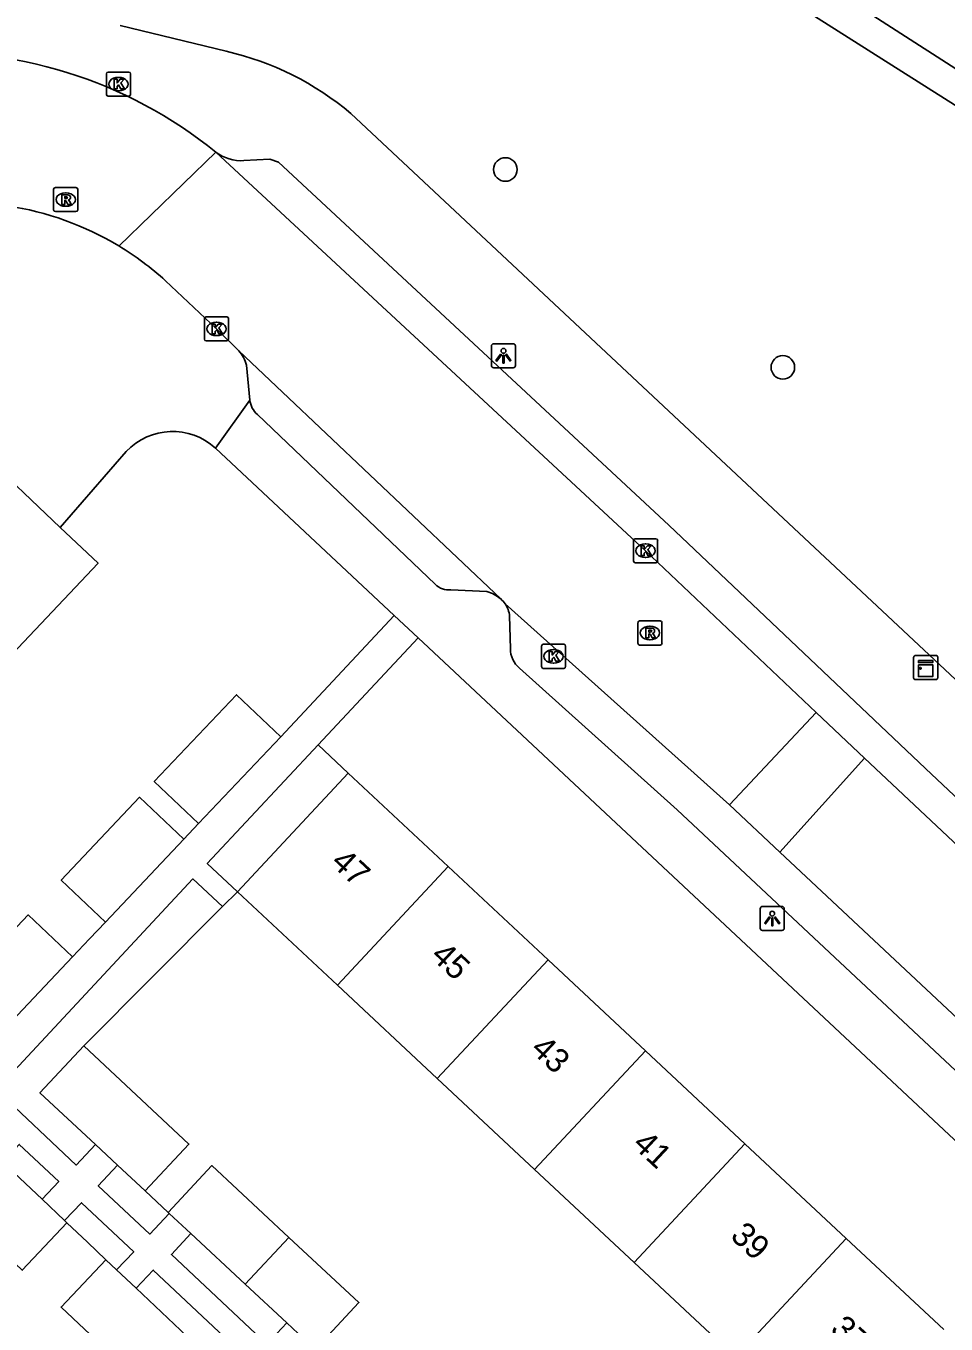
# Model space of a CAD drawing. Extents: x 159040 to 160094, y 381214 to 382518.
# Drawn here: x 159293.6 to 159331.8, y 381642.3 to 381696.1 of the extents above; entities that cross this region are included whole.
import ezdxf

# ---------------------------------------------------------------- set-up
doc = ezdxf.new("R2010")
doc.units = 0
for name, color, linetype in [('IMGEO_Boom', 7, 'Continuous'), ('IMGEO_Groenvoorziening', 7, 'Continuous'), ('IMGEO_Kast', 7, 'Continuous'), ('IMGEO_Kolk', 7, 'Continuous'), ('IMGEO_Lichtpunt', 7, 'Continuous'), ('IMGEO_Pand', 7, 'Continuous'), ('IMGEO_Pand_nummerreeks', 7, 'Continuous'), ('IMGEO_Pand_vergunning_verleend', 7, 'Continuous'), ('IMGEO_Rijbaan_lokaal_open', 7, 'Continuous'), ('IMGEO_Rioolput', 7, 'Continuous'), ('IMGEO_Voetpad_open', 7, 'Continuous')]:
    doc.layers.add(name, color=color, linetype=linetype)

msp = doc.modelspace()

# ---------------------------------------------------------------- linework, layer by layer
at = {"layer": 'IMGEO_Boom'}
for centre in [(159313.485, 381690.153), (159324.991, 381681.949)]:
    msp.add_circle(centre, 0.489, dxfattribs=at)
at = {"layer": 'IMGEO_Groenvoorziening'}
for points in [[(159254.046, 381759.615), (159260.693, 381743.327), (159266.405, 381734.562), (159282.762, 381724.205), (159299.545, 381713.576), (159301.255, 381712.388), (159329.506, 381694.484), (159334.296, 381691.448), (159363.507, 381691.862)], [(159305.726, 381666.298), (159306.973, 381665.131)], [(159301.759, 381659.594), (159296, 381653.818)], [(159298.548, 381647.807), (159299.504, 381646.915)], [(159295.298, 381646.49), (159296.153, 381645.681), (159296.923, 381644.952)]]:
    msp.add_lwpolyline(points, dxfattribs=at)
at = {"layer": 'IMGEO_Kast'}
for p, q in [((159330.489, 381670.007), (159331.33, 381670.007)), ((159331.33, 381670.007), (159330.489, 381670.007)), ((159331.414, 381669.932), (159331.414, 381669.091)), ((159331.414, 381669.091), (159331.414, 381669.932)), ((159330.414, 381669.082), (159330.414, 381669.923)), ((159330.414, 381669.923), (159330.414, 381669.082)), ((159331.339, 381669.007), (159330.498, 381669.007)), ((159330.498, 381669.007), (159331.339, 381669.007))]:
    msp.add_line(p, q, dxfattribs=at)
for points in [[(159330.609, 381669.797), (159331.209, 381669.797), (159331.209, 381669.712), (159330.609, 381669.712), (159330.609, 381669.797)], [(159330.609, 381669.622), (159331.209, 381669.622), (159331.209, 381669.133), (159330.609, 381669.133), (159330.609, 381669.622)]]:
    msp.add_lwpolyline(points, dxfattribs=at)
msp.add_circle((159330.693, 381669.471), 0.0377, dxfattribs=at)
for centre, start, end in [((159330.492, 381669.929), 92.4484, 184.2845), ((159330.492, 381669.929), 92.4484, 184.2845), ((159331.336, 381669.929), 2.4484, 94.2845), ((159331.336, 381669.929), 2.4484, 94.2845), ((159330.492, 381669.085), 182.4484, 274.2845), ((159330.492, 381669.085), 182.4484, 274.2845), ((159331.336, 381669.085), 272.4484, 4.2845), ((159331.336, 381669.085), 272.4484, 4.2845)]:
    msp.add_arc(centre, 0.0779, start, end, dxfattribs=at)
at = {"layer": 'IMGEO_Kolk'}
for p, q in [((159297.017, 381694.192), (159297.869, 381694.192)), ((159296.942, 381693.266), (159296.942, 381694.118)), ((159297.43, 381693.972), (159297.455, 381693.972)), ((159297.943, 381694.118), (159297.943, 381693.266)), ((159297.869, 381693.192), (159297.017, 381693.192)), ((159297.453, 381693.412), (159297.428, 381693.412)), ((159301.006, 381683.118), (159301.006, 381683.97)), ((159301.081, 381684.044), (159301.933, 381684.044)), ((159302.007, 381683.97), (159302.007, 381683.118)), ((159301.494, 381683.824), (159301.519, 381683.824)), ((159301.933, 381683.044), (159301.081, 381683.044)), ((159301.517, 381683.264), (159301.492, 381683.264)), ((159318.798, 381673.921), (159318.798, 381674.773)), ((159318.873, 381674.847), (159319.725, 381674.847)), ((159319.799, 381674.773), (159319.799, 381673.921)), ((159319.286, 381674.627), (159319.311, 381674.627)), ((159319.725, 381673.847), (159318.873, 381673.847)), ((159319.309, 381674.067), (159319.284, 381674.067)), ((159315.057, 381670.469), (159315.909, 381670.469)), ((159314.982, 381669.543), (159314.982, 381670.395)), ((159315.47, 381670.249), (159315.495, 381670.249)), ((159315.983, 381670.395), (159315.983, 381669.543)), ((159315.909, 381669.469), (159315.057, 381669.469)), ((159315.493, 381669.689), (159315.468, 381669.689))]:
    msp.add_line(p, q, dxfattribs=at)
for points in [[(159297.017, 381694.192), (159297.869, 381694.192)], [(159296.942, 381693.266), (159296.942, 381694.118)], [(159297.263, 381693.892), (159297.386, 381693.892), (159297.386, 381693.741), (159297.516, 381693.892), (159297.68, 381693.892), (159297.534, 381693.741), (159297.687, 381693.492), (159297.535, 381693.492), (159297.45, 381693.656), (159297.386, 381693.589), (159297.386, 381693.492), (159297.263, 381693.492), (159297.263, 381693.892)], [(159297.943, 381694.118), (159297.943, 381693.266)], [(159297.869, 381693.192), (159297.017, 381693.192)], [(159301.006, 381683.118), (159301.006, 381683.97)], [(159301.081, 381684.044), (159301.933, 381684.044)], [(159302.007, 381683.97), (159302.007, 381683.118)], [(159301.327, 381683.744), (159301.45, 381683.744), (159301.45, 381683.593), (159301.58, 381683.744), (159301.744, 381683.744), (159301.598, 381683.593), (159301.751, 381683.344), (159301.599, 381683.344), (159301.514, 381683.508), (159301.45, 381683.441), (159301.45, 381683.344), (159301.327, 381683.344), (159301.327, 381683.744)], [(159301.933, 381683.044), (159301.081, 381683.044)], [(159318.798, 381673.921), (159318.798, 381674.773)], [(159318.873, 381674.847), (159319.725, 381674.847)], [(159319.799, 381674.773), (159319.799, 381673.921)], [(159319.119, 381674.547), (159319.242, 381674.547), (159319.242, 381674.396), (159319.372, 381674.547), (159319.536, 381674.547), (159319.39, 381674.396), (159319.543, 381674.147), (159319.391, 381674.147), (159319.306, 381674.311), (159319.242, 381674.244), (159319.242, 381674.147), (159319.119, 381674.147), (159319.119, 381674.547)], [(159319.725, 381673.847), (159318.873, 381673.847)], [(159315.057, 381670.469), (159315.909, 381670.469)], [(159314.982, 381669.543), (159314.982, 381670.395)], [(159315.303, 381670.169), (159315.426, 381670.169), (159315.426, 381670.018), (159315.556, 381670.169), (159315.72, 381670.169), (159315.574, 381670.018), (159315.727, 381669.769), (159315.575, 381669.769), (159315.49, 381669.933), (159315.426, 381669.866), (159315.426, 381669.769), (159315.303, 381669.769), (159315.303, 381670.169)], [(159315.983, 381670.395), (159315.983, 381669.543)], [(159315.909, 381669.469), (159315.057, 381669.469)]]:
    msp.add_lwpolyline(points, dxfattribs=at)
for centre, start, end in [((159297.019, 381694.116), 91.552, 178.448), ((159297.019, 381694.116), 91.552, 178.448), ((159297.867, 381694.116), 1.552, 88.448), ((159297.867, 381694.116), 1.552, 88.448), ((159297.019, 381693.268), 181.552, 268.448), ((159297.019, 381693.268), 181.552, 268.448), ((159297.867, 381693.268), 271.552, 358.448), ((159297.867, 381693.268), 271.552, 358.448), ((159301.083, 381683.968), 91.552, 178.448), ((159301.083, 381683.968), 91.552, 178.448), ((159301.931, 381683.968), 1.552, 88.448), ((159301.931, 381683.968), 1.552, 88.448), ((159301.083, 381683.12), 181.552, 268.448), ((159301.083, 381683.12), 181.552, 268.448), ((159301.931, 381683.12), 271.552, 358.448), ((159301.931, 381683.12), 271.552, 358.448), ((159318.875, 381674.771), 91.552, 178.448), ((159318.875, 381674.771), 91.552, 178.448), ((159319.723, 381674.771), 1.552, 88.448), ((159319.723, 381674.771), 1.552, 88.448), ((159318.875, 381673.923), 181.552, 268.448), ((159318.875, 381673.923), 181.552, 268.448), ((159319.723, 381673.923), 271.552, 358.448), ((159319.723, 381673.923), 271.552, 358.448), ((159315.059, 381670.393), 91.552, 178.448), ((159315.059, 381670.393), 91.552, 178.448), ((159315.907, 381670.393), 1.552, 88.448), ((159315.907, 381670.393), 1.552, 88.448), ((159315.059, 381669.545), 181.552, 268.448), ((159315.059, 381669.545), 181.552, 268.448), ((159315.907, 381669.545), 271.552, 358.448), ((159315.907, 381669.545), 271.552, 358.448)]:
    msp.add_arc(centre, 0.0765, start, end, dxfattribs=at)
for centre, major_axis, ratio, start_param, end_param in [((159297.429, 381693.692), (-0.387, 0.002), 0.722429, 4.712389, 7.853982), ((159297.454, 381693.692), (-0.39, 0.002), 0.717154, 1.570796, 4.712389), ((159301.493, 381683.544), (-0.387, 0.002), 0.722429, 4.712389, 7.853982), ((159301.518, 381683.544), (-0.39, 0.002), 0.717154, 1.570796, 4.712389), ((159319.285, 381674.347), (-0.387, 0.002), 0.722429, 4.712389, 7.853982), ((159319.31, 381674.347), (-0.39, 0.002), 0.717154, 1.570796, 4.712389), ((159315.469, 381669.969), (-0.387, 0.002), 0.722429, 4.712389, 7.853982), ((159315.494, 381669.969), (-0.39, 0.002), 0.717154, 1.570796, 4.712389)]:
    msp.add_ellipse(centre, major_axis=major_axis, ratio=ratio, start_param=start_param, end_param=end_param, dxfattribs=at)
at = {"layer": 'IMGEO_Lichtpunt'}
for p, q in [((159313.809, 381682.931), (159313.001, 381682.931)), ((159313.809, 381682.931), (159313.001, 381682.931)), ((159312.907, 381682.836), (159312.907, 381682.029)), ((159312.907, 381682.836), (159312.907, 381682.029)), ((159313.903, 381682.029), (159313.903, 381682.836)), ((159313.903, 381682.029), (159313.903, 381682.836)), ((159313.001, 381681.935), (159313.809, 381681.935)), ((159313.001, 381681.935), (159313.809, 381681.935)), ((159324.052, 381659.505), (159324.052, 381658.698)), ((159324.052, 381659.505), (159324.052, 381658.698)), ((159324.954, 381659.6), (159324.146, 381659.6)), ((159324.954, 381659.6), (159324.146, 381659.6)), ((159325.048, 381658.698), (159325.048, 381659.505)), ((159325.048, 381658.698), (159325.048, 381659.505)), ((159324.146, 381658.604), (159324.954, 381658.604)), ((159324.146, 381658.604), (159324.954, 381658.604))]:
    msp.add_line(p, q, dxfattribs=at)
for points in [[(159313.281, 381682.5), (159313.32, 381682.472), (159313.132, 381682.21), (159313.094, 381682.237), (159313.281, 381682.5)], [(159313.383, 381682.452), (159313.43, 381682.452), (159313.43, 381682.13), (159313.383, 381682.13), (159313.383, 381682.452)], [(159313.493, 381682.472), (159313.531, 381682.499), (159313.718, 381682.237), (159313.679, 381682.209), (159313.493, 381682.472)], [(159324.426, 381659.169), (159324.465, 381659.141), (159324.277, 381658.879), (159324.239, 381658.906), (159324.426, 381659.169)], [(159324.638, 381659.141), (159324.676, 381659.168), (159324.863, 381658.906), (159324.824, 381658.878), (159324.638, 381659.141)], [(159324.528, 381659.121), (159324.575, 381659.121), (159324.575, 381658.799), (159324.528, 381658.799), (159324.528, 381659.121)]]:
    msp.add_lwpolyline(points, dxfattribs=at)
for centre in [(159313.406, 381682.634), (159324.551, 381659.303)]:
    msp.add_circle(centre, 0.0994, dxfattribs=at)
for centre, start, end in [((159313.001, 381682.836), 90, 180), ((159313.001, 381682.836), 90, 180), ((159313.809, 381682.836), 0, 90), ((159313.809, 381682.836), 0, 90), ((159313.001, 381682.029), 180, 270), ((159313.001, 381682.029), 180, 270), ((159313.809, 381682.029), 270, 0), ((159313.809, 381682.029), 270, 360), ((159324.146, 381659.505), 90, 180), ((159324.146, 381659.505), 90, 180), ((159324.954, 381659.505), 0, 90), ((159324.954, 381659.505), 0, 90), ((159324.146, 381658.698), 180, 270), ((159324.146, 381658.698), 180, 270), ((159324.954, 381658.698), 270, 0), ((159324.954, 381658.698), 270, 360)]:
    msp.add_arc(centre, 0.0946, start, end, dxfattribs=at)
at = {"layer": 'IMGEO_Pand'}
for points in [[(159291.702, 381678.458), (159295.025, 381675.313)], [(159295.025, 381675.313), (159296.595, 381673.828), (159292.562, 381669.565)], [(159304.176, 381666.638), (159302.337, 381668.378), (159298.927, 381664.774), (159300.766, 381663.034)], [(159300.766, 381663.034), (159304.176, 381666.638)], [(159302.373, 381660.209), (159306.973, 381665.131)], [(159306.973, 381665.131), (159311.117, 381661.258)], [(159300.152, 381662.385), (159298.313, 381664.125), (159295.068, 381660.695), (159296.907, 381658.955)], [(159296.907, 381658.955), (159300.152, 381662.385)], [(159306.518, 381656.336), (159311.117, 381661.258)], [(159311.117, 381661.258), (159315.262, 381657.384)], [(159306.518, 381656.336), (159302.373, 381660.209)], [(159295.537, 381657.507), (159293.698, 381659.247), (159290.481, 381655.846)], [(159292.32, 381654.107), (159295.537, 381657.507)], [(159310.663, 381652.462), (159315.262, 381657.384)], [(159315.262, 381657.384), (159319.291, 381653.619)], [(159310.663, 381652.462), (159306.518, 381656.336)], [(159296.49, 381649.727), (159294.187, 381651.875), (159296, 381653.818)], [(159296, 381653.818), (159300.363, 381649.749), (159298.548, 381647.807)], [(159319.291, 381653.619), (159314.692, 381648.697)], [(159319.291, 381653.619), (159323.418, 381649.763)], [(159314.692, 381648.697), (159310.663, 381652.462)], [(159296.49, 381649.727), (159297.408, 381648.87)], [(159318.819, 381644.84), (159323.418, 381649.763)], [(159323.418, 381649.763), (159327.622, 381645.834)], [(159294.273, 381647.46), (159292.641, 381649.003)], [(159298.548, 381647.807), (159297.408, 381648.87)], [(159299.504, 381646.915), (159301.319, 381648.857), (159304.512, 381645.879)], [(159318.819, 381644.84), (159314.692, 381648.697)], [(159295.298, 381646.49), (159293.452, 381644.514), (159290.242, 381647.551)], [(159295.205, 381646.578), (159294.273, 381647.46)], [(159299.546, 381646.876), (159299.504, 381646.915)], [(159299.546, 381646.876), (159300.444, 381646.038)], [(159295.205, 381646.578), (159295.298, 381646.49)], [(159300.444, 381646.038), (159302.697, 381643.937)], [(159302.697, 381643.937), (159304.512, 381645.879)], [(159304.512, 381645.879), (159307.409, 381643.176), (159305.594, 381641.234)], [(159323.023, 381640.912), (159327.622, 381645.834)], [(159327.622, 381645.834), (159331.664, 381642.058)], [(159296.923, 381644.952), (159295.065, 381642.988), (159298.433, 381639.802)], [(159296.923, 381644.952), (159297.367, 381644.532)], [(159323.023, 381640.912), (159318.819, 381644.84)], [(159298.171, 381643.771), (159297.367, 381644.532)], [(159300.278, 381641.778), (159298.171, 381643.771)], [(159302.697, 381643.937), (159304.418, 381642.331)], [(159304.418, 381642.331), (159305.594, 381641.234)]]:
    msp.add_lwpolyline(points, dxfattribs=at)
at = {"layer": 'IMGEO_Pand_vergunning_verleend'}
msp.add_lwpolyline([(159293.854, 381718.952), (159300.878, 381730.325), (159309.701, 381724.654), (159308.093, 381722.153), (159329.394, 381708.463), (159336.626, 381719.716), (159347.879, 381712.483), (159335.028, 381692.488), (159293.854, 381718.952)], dxfattribs=at)
at = {"layer": 'IMGEO_Rijbaan_lokaal_open'}
for points in [[(159297.457, 381686.981), (159301.481, 381690.871)], [(159326.371, 381667.639), (159319.282, 381674.363), (159301.481, 381690.871)], [(159299.39, 381685.543), (159301.507, 381683.544), (159302.437, 381682.629)], [(159302.437, 381682.629), (159313.293, 381672.348)], [(159313.481, 381672.145), (159322.773, 381663.808)], [(159322.773, 381663.808), (159326.371, 381667.639)], [(159328.37, 381665.744), (159326.371, 381667.639)], [(159328.37, 381665.744), (159324.865, 381661.853)], [(159347.221, 381648.04), (159328.37, 381665.744)], [(159322.773, 381663.808), (159324.865, 381661.853)], [(159324.865, 381661.853), (159343.743, 381644.17)]]:
    msp.add_lwpolyline(points, dxfattribs=at)
for centre, radius, start, end in [((159289.866, 381676.584), 18.413, 50.8897, 94.7314), ((159290.979, 381676.253), 12.532, 58.8769, 81.462), ((159291.013, 381676.301), 12.474, 47.8119, 58.8954), ((159312.408, 381671.34), 1.341, 36.8811, 48.725)]:
    msp.add_arc(centre, radius, start, end, dxfattribs=at)
at = {"layer": 'IMGEO_Rioolput'}
for p, q in [((159294.754, 381688.48), (159294.754, 381689.332)), ((159294.829, 381689.406), (159295.681, 381689.406)), ((159295.755, 381689.332), (159295.755, 381688.48)), ((159295.242, 381689.186), (159295.267, 381689.186)), ((159295.681, 381688.406), (159294.829, 381688.406)), ((159295.265, 381688.626), (159295.24, 381688.626)), ((159318.978, 381670.513), (159318.978, 381671.365)), ((159319.053, 381671.439), (159319.905, 381671.439)), ((159319.466, 381671.219), (159319.491, 381671.219)), ((159319.979, 381671.365), (159319.979, 381670.513)), ((159319.489, 381670.659), (159319.464, 381670.659)), ((159319.905, 381670.439), (159319.053, 381670.439))]:
    msp.add_line(p, q, dxfattribs=at)
for points in [[(159294.754, 381688.48), (159294.754, 381689.332)], [(159294.829, 381689.406), (159295.681, 381689.406)], [(159295.755, 381689.332), (159295.755, 381688.48)], [(159295.343, 381689.104), (159295.091, 381689.106), (159295.091, 381688.706)], [(159295.091, 381688.706), (159295.215, 381688.706), (159295.215, 381688.868), (159295.226, 381688.868)], [(159295.269, 381689.025), (159295.215, 381689.025), (159295.215, 381688.944)], [(159295.215, 381688.944), (159295.267, 381688.944)], [(159295.273, 381688.839), (159295.344, 381688.706), (159295.484, 381688.706), (159295.419, 381688.832)], [(159295.681, 381688.406), (159294.829, 381688.406)], [(159318.978, 381670.513), (159318.978, 381671.365)], [(159319.053, 381671.439), (159319.905, 381671.439)], [(159319.567, 381671.137), (159319.315, 381671.139), (159319.315, 381670.739)], [(159319.493, 381671.058), (159319.439, 381671.058), (159319.439, 381670.977)], [(159319.979, 381671.365), (159319.979, 381670.513)], [(159319.315, 381670.739), (159319.439, 381670.739), (159319.439, 381670.901), (159319.45, 381670.901)], [(159319.439, 381670.977), (159319.491, 381670.977)], [(159319.497, 381670.872), (159319.568, 381670.739), (159319.708, 381670.739), (159319.643, 381670.865)], [(159319.905, 381670.439), (159319.053, 381670.439)]]:
    msp.add_lwpolyline(points, dxfattribs=at)
for centre, radius, start, end in [((159294.831, 381689.33), 0.0765, 91.552, 178.448), ((159294.831, 381689.33), 0.0765, 91.552, 178.448), ((159295.679, 381689.33), 0.0765, 1.552, 88.448), ((159295.679, 381689.33), 0.0765, 1.552, 88.448), ((159295.225, 381688.815), 0.0533, 26.0293, 88.6989), ((159295.251, 381689.133), 0.19, 274.7715, 282.9687), ((159295.275, 381688.929), 0.0964, 77.0061, 93.1865), ((159295.289, 381688.986), 0.0378, 276.6634, 79.6772), ((159295.342, 381688.994), 0.109, 350.3612, 89.416), ((159295.34, 381688.994), 0.112, 277.5842, 350.9817), ((159295.324, 381688.779), 0.108, 29.5134, 73.7905), ((159294.831, 381688.482), 0.0765, 181.552, 268.448), ((159294.831, 381688.482), 0.0765, 181.552, 268.448), ((159295.679, 381688.482), 0.0765, 271.552, 358.448), ((159295.679, 381688.482), 0.0765, 271.552, 358.448), ((159319.055, 381671.363), 0.0765, 91.552, 178.448), ((159319.055, 381671.363), 0.0765, 91.552, 178.448), ((159319.499, 381670.962), 0.0964, 77.0061, 93.1865), ((159319.513, 381671.019), 0.0378, 276.6634, 79.6772), ((159319.566, 381671.027), 0.109, 350.3612, 89.416), ((159319.564, 381671.027), 0.112, 277.5842, 350.9817), ((159319.903, 381671.363), 0.0765, 1.552, 88.448), ((159319.903, 381671.363), 0.0765, 1.552, 88.448), ((159319.055, 381670.515), 0.0765, 181.552, 268.448), ((159319.055, 381670.515), 0.0765, 181.552, 268.448), ((159319.449, 381670.848), 0.0533, 26.0293, 88.6989), ((159319.475, 381671.166), 0.19, 274.7715, 282.9687), ((159319.548, 381670.812), 0.108, 29.5134, 73.7905), ((159319.903, 381670.515), 0.0765, 271.552, 358.448), ((159319.903, 381670.515), 0.0765, 271.552, 358.448)]:
    msp.add_arc(centre, radius, start, end, dxfattribs=at)
for centre, major_axis, ratio, start_param, end_param in [((159295.241, 381688.906), (-0.387, 0.002), 0.722429, 4.712389, 7.853982), ((159295.266, 381688.906), (-0.39, 0.002), 0.717154, 1.570796, 4.712389), ((159319.465, 381670.939), (-0.387, 0.002), 0.722429, 4.712389, 7.853982), ((159319.49, 381670.939), (-0.39, 0.002), 0.717154, 1.570796, 4.712389)]:
    msp.add_ellipse(centre, major_axis=major_axis, ratio=ratio, start_param=start_param, end_param=end_param, dxfattribs=at)
at = {"layer": 'IMGEO_Voetpad_open'}
for points in [[(159297.509, 381696.125), (159301.914, 381695.053)], [(159307.081, 381692.477), (159333.002, 381668.212), (159333.349, 381667.887), (159334.91, 381666.426), (159337.645, 381663.865)], [(159346.95, 381650.263), (159336.6, 381659.961), (159330.906, 381665.319), (159320.266, 381675.411), (159304.079, 381690.45), (159303.722, 381690.575), (159302.644, 381690.52)], [(159302.751, 381682.04), (159302.886, 381680.595)], [(159302.886, 381680.595), (159301.466, 381678.598)], [(159303.207, 381679.992), (159310.574, 381672.96)], [(159301.466, 381678.598), (159308.878, 381671.662)], [(159297.767, 381678.459), (159295.025, 381675.313)], [(159311.23, 381672.727), (159312.714, 381672.653)], [(159304.176, 381666.638), (159308.878, 381671.662)], [(159308.878, 381671.662), (159309.873, 381670.73)], [(159313.661, 381671.644), (159313.698, 381670.285)], [(159309.873, 381670.73), (159305.726, 381666.298)], [(159309.873, 381670.73), (159341.159, 381641.45)], [(159314.075, 381669.48), (159320.61, 381663.612), (159331.275, 381653.611), (159341.081, 381644.432)], [(159305.726, 381666.298), (159302.935, 381663.316), (159301.124, 381661.375), (159302.373, 381660.209)], [(159300.152, 381662.385), (159300.766, 381663.034)], [(159301.759, 381659.594), (159300.531, 381660.74), (159292.369, 381651.992), (159295.691, 381648.875), (159296.49, 381649.727)], [(159302.373, 381660.209), (159301.759, 381659.594)], [(159295.537, 381657.507), (159296.245, 381658.255), (159296.907, 381658.955)], [(159294.273, 381647.46), (159294.968, 381648.194), (159293.33, 381649.731), (159292.641, 381649.003)], [(159297.408, 381648.87), (159296.607, 381648.016), (159298.739, 381646.016), (159299.546, 381646.876)], [(159297.367, 381644.532), (159298.074, 381645.28), (159295.903, 381647.317), (159295.205, 381646.578)], [(159300.444, 381646.038), (159299.635, 381645.176), (159303.598, 381641.457), (159304.418, 381642.331)], [(159302.472, 381639.703), (159303.199, 381640.472), (159298.882, 381644.522), (159298.171, 381643.771)]]:
    msp.add_lwpolyline(points, dxfattribs=at)
for centre, radius, start, end in [((159299.172, 381683.083), 12.28, 49.9052, 77.0978), ((159302.55, 381692.311), 1.794, 233.4106, 273.0011), ((159301.437, 381681.718), 1.353, 13.785, 42.3397), ((159303.825, 381680.708), 0.945, 186.8484, 229.2077), ((159299.687, 381676.663), 2.629, 47.3951, 136.909), ((159311.138, 381673.509), 0.788, 224.2181, 276.6736), ((159312.39, 381671.335), 1.357, 48.2713, 76.1709), ((159312.505, 381671.511), 1.164, 6.5435, 32.9813), ((159314.68, 381670.254), 0.983, 178.2019, 231.9877)]:
    msp.add_arc(centre, radius, start, end, dxfattribs=at)

# ---------------------------------------------------------------- texts
at = {"layer": 'IMGEO_Pand_nummerreeks'}
for s, p in [('47', (159306.201, 381661.364)), ('45', (159310.343, 381657.494)), ('43', (159314.484, 381653.623)), ('41', (159318.709, 381649.676)), ('39', (159322.768, 381645.882)), ('37', (159326.909, 381642.012))]:
    msp.add_text(s, height=1, rotation=316.9393, dxfattribs=at).set_placement(p)

doc.saveas('drawing.dxf')
